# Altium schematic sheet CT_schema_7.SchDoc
size 278 x 170 mm
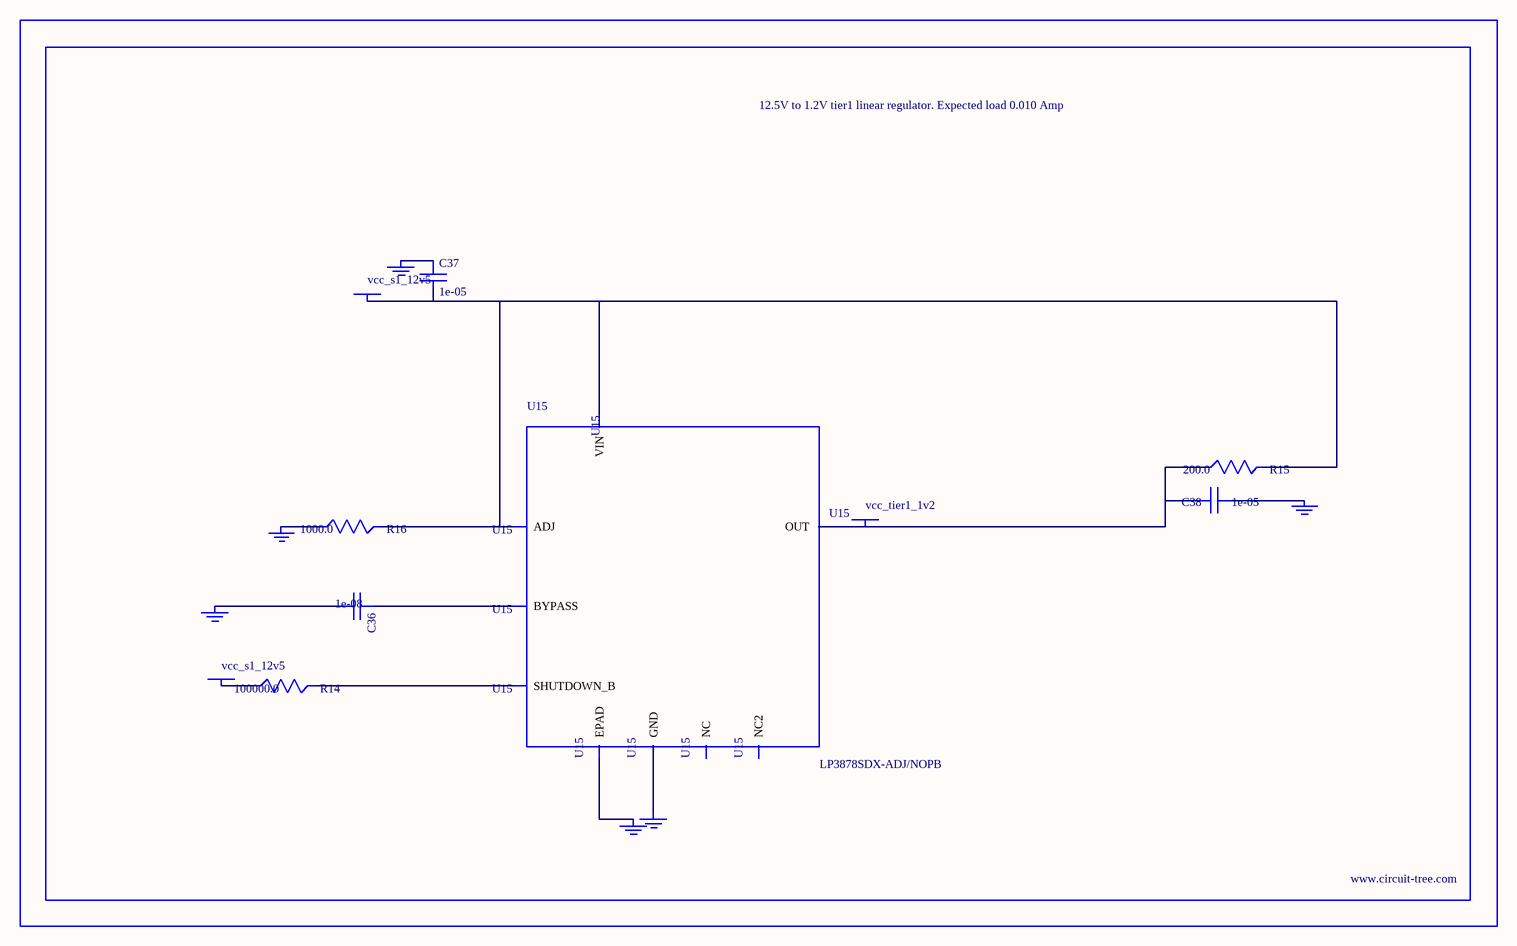
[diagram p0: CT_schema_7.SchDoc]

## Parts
BORDER6  (no value)
C36  1e-08  [C0402]
C37  1e-05  [C1210]
C38  1e-05  [C0805]
GND_INSTANCE_6_0  (no value)
GND_INSTANCE_6_1  (no value)
GND_INSTANCE_6_2  (no value)
GND_INSTANCE_6_3  (no value)
GND_INSTANCE_6_4  (no value)
GND_INSTANCE_6_5  (no value)
POWER_INSTANCE_6_0  vcc_s1_12v5
POWER_INSTANCE_6_1  vcc_s1_12v5
POWER_INSTANCE_6_2  vcc_tier1_1v2
R14  100000.0  [R0603]
R15  200.0  [R0603]
R16  1000.0  [R0603]
U15  LP3878SDX-ADJ/NOPB  [WSON-8]

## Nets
NetC36_1: C36.1 U15.1(BYPASS)
NetC36_2: C36.2 GND_INSTANCE_6_0.0(GND)
NetC37_1: C37.1 GND_INSTANCE_6_1.0(GND)
NetC37_2: C37.2 POWER_INSTANCE_6_0.0(PWR) R15.2 R16.2 U15.4(VIN) U15.6(ADJ)
NetC38_1: C38.1 GND_INSTANCE_6_2.0(GND)
NetC38_2: C38.2 POWER_INSTANCE_6_2.0(PWR) R15.1 U15.5(OUT)
NetGND_INSTANCE_6_3_0: GND_INSTANCE_6_3.0(GND) R16.1
NetGND_INSTANCE_6_4_0: GND_INSTANCE_6_4.0(GND) U15.PAD(EPAD)
NetGND_INSTANCE_6_5_0: GND_INSTANCE_6_5.0(GND) U15.3(GND)
NetPOWER_INSTANCE_6_1_0: POWER_INSTANCE_6_1.0(PWR) R14.1
NetR14_2: R14.2 U15.8(SHUTDOWN_B)

Not connected (* = marked no-connect by the designer): U15 2(NC) 7(NC2)

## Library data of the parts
BORDER6 = BORDER_PAGE6
C36 = C0402C103K3RAC
C37 = C1210C106K5PACTU
C38 = GRM219R60J106ME19D
GND_INSTANCE_6_0-GND_INSTANCE_6_5 = GND
POWER_INSTANCE_6_0-POWER_INSTANCE_6_2 = PWR
R14 = RC0603JR-07100KL
R15 = RC0603JR-07200RL
R16 = RC0603JR-071KL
